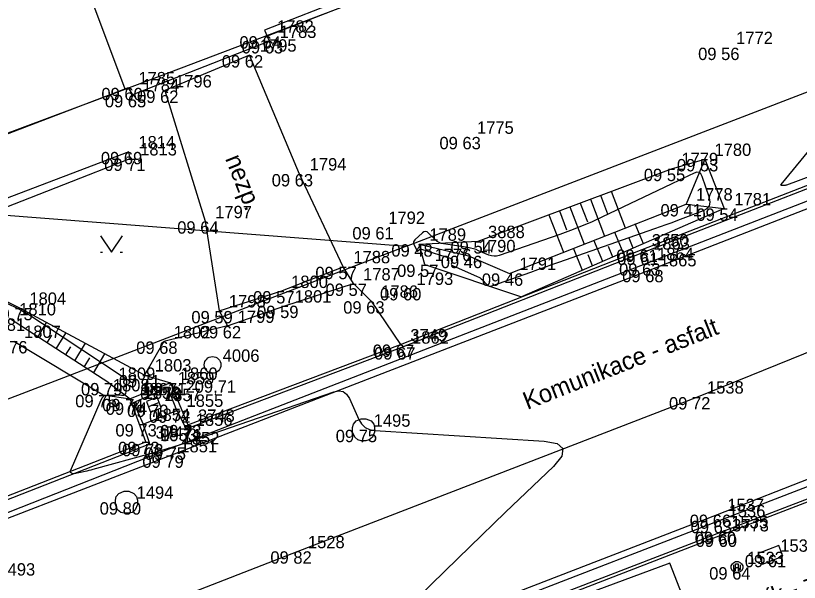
# Model space of a CAD drawing. Extents: x -703403 to -701924, y -1022520 to -1021856.
# Drawn here: x -702994.62 to -702976.87, y -1022001.97 to -1021989.15 of the extents above; entities that cross this region are included whole.
import ezdxf

# ---------------------------------------------------------------- set-up
doc = ezdxf.new("R2010")
doc.units = 0
for name, color, linetype in [('Ex_Minor Contours', 7, 'Continuous'), ('Z_bodove_pole', 7, 'Continuous'), ('Z_bodove_pole_cisla', 7, 'Continuous'), ('Z_bodove_pole_vysky', 7, 'Continuous'), ('Z_body', 7, 'Continuous'), ('Z_body_cisla', 7, 'Continuous'), ('Z_body_vysky_redukovane', 7, 'Continuous'), ('Z_budova', 7, 'Continuous'), ('Z_hrany_paty', 7, 'Continuous'), ('Z_katastr_hranice', 7, 'Continuous'), ('Z_katastr_vnitrni_kresba', 7, 'Continuous'), ('Z_komunikace', 7, 'Continuous'), ('Z_komunikace_osa', 7, 'Continuous'), ('Z_obruba', 7, 'Continuous'), ('Z_pilire', 7, 'Continuous'), ('Z_ploty', 7, 'Continuous'), ('Z_popisy', 7, 'Continuous'), ('Z_rozhranni', 7, 'Continuous'), ('Z_site_kanalizace_znaky', 7, 'Continuous'), ('Z_sloupy', 7, 'Continuous'), ('Z_technicke_srafy', 7, 'Continuous'), ('Z_vstupy', 7, 'Continuous'), ('Z_zlabek', 7, 'Continuous'), ('Z_znaky_kultur', 7, 'Continuous')]:
    doc.layers.add(name, color=color, linetype=linetype)

# ---------------------------------------------------------------- blocks, each defined once
blk = doc.blocks.new('POINT_DISPLAY')
blk.add_line((0, 0), (0, 0))
blk = doc.blocks.new('Z666')
for p, q in [((-0.25, 0.13), (-0.25, -0.13)), ((0.25, 0.13), (-0.25, 0.13)), ((0.25, -0.13), (0.25, 0.13)), ((-0.25, -0.13), (0.25, -0.13))]:
    blk.add_line(p, q)
blk = doc.blocks.new('Z620')
for p, q in [((-0.23, 0.13), (-0.17, 0.2)), ((-0.17, 0.2), (-0.05, 0.25)), ((-0.05, 0.25), (0.05, 0.25)), ((0.05, 0.25), (0.17, 0.2)), ((0.17, 0.2), (0.23, 0.13)), ((-0.25, 0.05), (-0.23, 0.13)), ((-0.25, -0.05), (-0.25, 0.05)), ((0.23, 0.13), (0.25, 0.05)), ((0.25, 0.05), (0.25, -0.05)), ((-0.2, -0.17), (-0.25, -0.05)), ((-0.13, -0.23), (-0.2, -0.17)), ((0.2, -0.17), (0.13, -0.23)), ((0.25, -0.05), (0.2, -0.17)), ((-0.05, -0.25), (-0.13, -0.23)), ((0.05, -0.25), (-0.05, -0.25)), ((0.13, -0.23), (0.05, -0.25))]:
    blk.add_line(p, q)
blk = doc.blocks.new('Z46260')
for p, q in [((0.13, 0.13), (-0.13, 0.13)), ((-0.13, 0.13), (-0.13, -0.13)), ((0.13, 0), (-0.13, 0)), ((0.13, -0.13), (0.13, 0.13)), ((-0.13, -0.13), (0.13, -0.13))]:
    blk.add_line(p, q)
blk = doc.blocks.new('Z601')
for p, q in [((-0.13, 0.03), (-0.1, 0.08)), ((-0.13, -0.03), (-0.13, 0.03)), ((-0.1, 0.08), (-0.08, 0.1)), ((-0.08, 0.1), (-0.03, 0.13)), ((-0.08, 0.05), (-0.08, -0.05)), ((-0.03, 0.13), (0.03, 0.13)), ((-0.03, -0.08), (-0.03, 0.08)), ((-0.03, 0.08), (0.03, 0.08)), ((0.03, 0.13), (0.08, 0.1)), ((0.03, 0.08), (0.03, -0.08)), ((0.08, 0.1), (0.1, 0.08)), ((0.08, -0.05), (0.08, 0.05)), ((0.1, 0.08), (0.13, 0.03)), ((0.13, 0.03), (0.13, -0.03)), ((-0.1, -0.08), (-0.13, -0.03)), ((-0.08, -0.1), (-0.1, -0.08)), ((-0.08, -0.05), (-0.03, -0.08)), ((-0.03, -0.13), (-0.08, -0.1)), ((0.03, -0.13), (-0.03, -0.13)), ((0.03, -0.08), (0.08, -0.05)), ((0.08, -0.1), (0.03, -0.13)), ((0.1, -0.08), (0.08, -0.1)), ((0.13, -0.03), (0.1, -0.08))]:
    blk.add_line(p, q)
blk = doc.blocks.new('Z314')
for p, q in [((-0.25, 0.17), (0, -0.2)), ((0, -0.2), (0.25, 0.17)), ((-0.25, -0.2), (-0.2, -0.2)), ((0.2, -0.2), (0.25, -0.2))]:
    blk.add_line(p, q)
blk = doc.blocks.new('Z101')
for radius in [0.188, 0.0025]:
    blk.add_circle((0, 0), radius)

msp = doc.modelspace()

# ---------------------------------------------------------------- linework, layer by layer
at = {"layer": 'Ex_Minor Contours'}
for points in [[(-702972.675, -1021991.314), (-702977.158, -1021992.979), (-702977.172, -1021992.984), (-702977.185, -1021992.987), (-702977.199, -1021992.988), (-702977.213, -1021992.988), (-702977.27, -1021992.987), (-702977.282, -1021992.985), (-702977.287, -1021992.98), (-702977.287, -1021992.973), (-702977.281, -1021992.964), (-702976.132, -1021991.569)], [(-702994.835, -1021995.642), (-702994.554, -1021995.785), (-702994.279, -1021995.941), (-702994.011, -1021996.11), (-702992.184, -1021997.318), (-702992.15, -1021997.347), (-702992.126, -1021997.381), (-702992.113, -1021997.42), (-702992.11, -1021997.465), (-702992.121, -1021997.654), (-702992.129, -1021997.695), (-702992.148, -1021997.724), (-702992.179, -1021997.74), (-702992.221, -1021997.745), (-702992.512, -1021997.735), (-702992.571, -1021997.74), (-702992.621, -1021997.761), (-702992.661, -1021997.797), (-702992.691, -1021997.848), (-702993.386, -1021999.459), (-702993.387, -1021999.463), (-702993.386, -1021999.466), (-702993.384, -1021999.474), (-702993.382, -1021999.477), (-702993.379, -1021999.479), (-702993.332, -1021999.506), (-702993.323, -1021999.509), (-702993.315, -1021999.512), (-702993.305, -1021999.512), (-702993.296, -1021999.511), (-702993.043, -1021999.456), (-702992.997, -1021999.446), (-702992.952, -1021999.435), (-702992.907, -1021999.423), (-702992.862, -1021999.411), (-702991.541, -1021999.049), (-702991.306, -1021998.983), (-702991.072, -1021998.912), (-702990.84, -1021998.839), (-702990.609, -1021998.761), (-702987.413, -1021997.658), (-702987.299, -1021997.635), (-702987.202, -1021997.653), (-702987.123, -1021997.711), (-702987.06, -1021997.81), (-702986.847, -1021998.283), (-702986.784, -1021998.388), (-702986.702, -1021998.465), (-702986.601, -1021998.514), (-702986.481, -1021998.536), (-702982.648, -1021998.78), (-702982.354, -1021998.833), (-702982.222, -1021998.945), (-702982.25, -1021999.117), (-702982.44, -1021999.347), (-702983.523, -1022000.387), (-702983.793, -1022000.647), (-702984.063, -1022000.908), (-702984.333, -1022001.169), (-702984.602, -1022001.43), (-702986.726, -1022003.497)]]:
    msp.add_lwpolyline(points, dxfattribs=at)
msp.add_lwpolyline([(-702983.924, -1021995.255), (-702983.896, -1021995.267), (-702983.865, -1021995.27), (-702983.833, -1021995.263), (-702982.948, -1021994.949), (-702982.789, -1021994.892), (-702982.63, -1021994.836), (-702982.471, -1021994.78), (-702982.312, -1021994.725), (-702980.144, -1021993.966), (-702980.012, -1021993.919), (-702979.881, -1021993.872), (-702979.749, -1021993.824), (-702979.619, -1021993.775), (-702979.04, -1021993.557), (-702978.955, -1021993.51), (-702978.904, -1021993.447), (-702978.887, -1021993.367), (-702978.905, -1021993.271), (-702979.069, -1021992.783), (-702979.097, -1021992.727), (-702979.136, -1021992.695), (-702979.186, -1021992.689), (-702979.247, -1021992.708), (-702979.51, -1021992.833), (-702979.576, -1021992.864), (-702979.642, -1021992.896), (-702979.708, -1021992.927), (-702979.774, -1021992.959), (-702981.325, -1021993.7), (-702981.563, -1021993.81), (-702981.804, -1021993.913), (-702982.049, -1021994.009), (-702982.295, -1021994.099), (-702983.665, -1021994.574), (-702983.725, -1021994.589), (-702983.784, -1021994.592), (-702983.843, -1021994.584), (-702983.901, -1021994.565), (-702984.134, -1021994.465), (-702984.192, -1021994.442), (-702984.252, -1021994.423), (-702984.313, -1021994.407), (-702984.375, -1021994.396), (-702984.928, -1021994.313), (-702984.979, -1021994.301), (-702985.026, -1021994.282), (-702985.069, -1021994.255), (-702985.109, -1021994.222), (-702985.265, -1021994.065), (-702985.3, -1021994.039), (-702985.335, -1021994.03), (-702985.371, -1021994.037), (-702985.407, -1021994.062), (-702985.578, -1021994.219), (-702985.596, -1021994.24), (-702985.606, -1021994.264), (-702985.607, -1021994.289), (-702985.599, -1021994.316), (-702985.536, -1021994.462), (-702985.531, -1021994.471), (-702985.524, -1021994.475), (-702985.517, -1021994.475), (-702985.508, -1021994.469), (-702985.47, -1021994.438), (-702985.46, -1021994.432), (-702985.45, -1021994.428), (-702985.439, -1021994.427), (-702985.428, -1021994.43), (-702984.754, -1021994.642), (-702984.74, -1021994.649), (-702984.731, -1021994.659), (-702984.728, -1021994.671), (-702984.73, -1021994.687), (-702984.75, -1021994.755), (-702984.752, -1021994.77), (-702984.749, -1021994.784), (-702984.741, -1021994.794), (-702984.727, -1021994.803), (-702984.162, -1021995.046), (-702984.13, -1021995.062), (-702984.1, -1021995.08), (-702984.072, -1021995.102), (-702984.047, -1021995.127), (-702983.949, -1021995.234)], close=True, dxfattribs=at)
at = {"layer": 'Z_budova'}
msp.add_line((-702992.07, -1021990.78), (-702997.53, -1021992.86), dxfattribs=at)
at = {"layer": 'Z_hrany_paty'}
for p, q in [((-702979.76, -1021992.61), (-702979.01, -1021992.39)), ((-702979.01, -1021992.39), (-702979.43, -1021993.41)), ((-702979.01, -1021992.39), (-702978.57, -1021993.51)), ((-702984.14, -1021994.25), (-702979.76, -1021992.61)), ((-702983.43, -1021994.98), (-702979.43, -1021993.41)), ((-702978.57, -1021993.51), (-702983.16, -1021995.51)), ((-702979.43, -1021993.41), (-702978.57, -1021993.51)), ((-702985.48, -1021994.32), (-702984.14, -1021994.25)), ((-702985.48, -1021994.32), (-702984.36, -1021994.58)), ((-702985.35, -1021994.78), (-702985.48, -1021994.32)), ((-702984.36, -1021994.58), (-702983.43, -1021994.98)), ((-702985.35, -1021994.78), (-702983.16, -1021995.51)), ((-702992.51, -1021997.46), (-702994.76, -1021996)), ((-702992.51, -1021997.46), (-702992.03, -1021997.82))]:
    msp.add_line(p, q, dxfattribs=at)
at = {"layer": 'Z_katastr_hranice'}
for p, q in [((-702985.77, -1021994.36), (-702958.49, -1021983.88)), ((-702992.14, -1021990.81), (-702986.88, -1021988.82)), ((-702997.54, -1021992.82), (-702992.14, -1021990.81)), ((-702998.95, -1021993.34), (-702985.77, -1021994.36)), ((-702985.77, -1021994.36), (-703007.65, -1022002.76)), ((-702979.8, -1022001.54), (-702991.54, -1022005.86)), ((-702978.94, -1022003.75), (-702979.8, -1022001.54))]:
    msp.add_line(p, q, dxfattribs=at)
at = {"layer": 'Z_katastr_vnitrni_kresba'}
msp.add_line((-702992.14, -1021990.81), (-703000.14, -1021969.33), dxfattribs=at)
at = {"layer": 'Z_komunikace'}
for p, q in [((-702980.25, -1021994.9), (-702966.7, -1021989.63)), ((-702991.12, -1021999.1), (-702980.25, -1021994.9)), ((-702978.72, -1022000.44), (-702970.7, -1021997.29)), ((-702998.41, -1022001.91), (-702991.12, -1021999.1)), ((-702987.66, -1022003.88), (-702978.72, -1022000.44))]:
    msp.add_line(p, q, dxfattribs=at)
at = {"layer": 'Z_komunikace_osa'}
for p, q in [((-702979.19, -1021997.78), (-702967.67, -1021993.13)), ((-702988.22, -1022001.27), (-702979.19, -1021997.78)), ((-702994.51, -1022003.7), (-702988.22, -1022001.27))]:
    msp.add_line(p, q, dxfattribs=at)
at = {"layer": 'Z_obruba'}
for p, q in [((-702980.43, -1021994.44), (-702966.9, -1021989.18)), ((-702980.32, -1021994.75), (-702966.79, -1021989.5)), ((-702992.06, -1021992.23), (-702996.78, -1021994.02)), ((-702992.03, -1021992.38), (-702992.06, -1021992.23)), ((-702996.72, -1021994.22), (-702992.03, -1021992.38)), ((-702985.9, -1021996.59), (-702980.43, -1021994.44)), ((-702991.07, -1021998.92), (-702980.32, -1021994.75)), ((-702990.72, -1021998.41), (-702985.9, -1021996.59)), ((-702991.11, -1021997.46), (-702992.03, -1021997.82)), ((-702991.11, -1021997.46), (-702990.72, -1021998.41)), ((-702978.7, -1022000.58), (-702970.64, -1021997.47)), ((-702991.67, -1021998.79), (-702992.03, -1021997.82)), ((-702978.61, -1022000.89), (-702970.57, -1021997.79)), ((-702998.54, -1022001.48), (-702991.67, -1021998.79)), ((-702998.44, -1022001.82), (-702991.07, -1021998.92)), ((-702987.62, -1022004.02), (-702978.7, -1022000.58)), ((-702984.36, -1022003.11), (-702978.61, -1022000.89))]:
    msp.add_line(p, q, dxfattribs=at)
at = {"layer": 'Z_ploty'}
for p, q in [((-702986.83, -1021988.63), (-702988.98, -1021989.47)), ((-702986.78, -1021988.77), (-702988.92, -1021989.61)), ((-702988.98, -1021989.47), (-702988.92, -1021989.61))]:
    msp.add_line(p, q, dxfattribs=at)
at = {"layer": 'Z_rozhranni'}
for p, q in [((-702989.32, -1021990.04), (-702991.24, -1021990.84)), ((-702988.19, -1021992.73), (-702989.32, -1021990.04)), ((-702991.24, -1021990.84), (-702990.33, -1021993.8)), ((-702987.2, -1021994.83), (-702988.19, -1021992.73)), ((-702990.33, -1021993.8), (-702990.01, -1021995.83)), ((-702994.54, -1021995.76), (-702997.09, -1021994.51)), ((-702986.97, -1021995.21), (-702987.2, -1021994.83)), ((-702986.57, -1021995.61), (-702986.97, -1021995.21)), ((-702986.57, -1021995.61), (-702985.9, -1021996.59)), ((-702991.7, -1021997.28), (-702994.54, -1021995.76)), ((-702990.01, -1021995.83), (-702989.82, -1021996.17)), ((-702989.82, -1021996.17), (-702991.26, -1021996.52)), ((-702994.66, -1021996.51), (-702992.64, -1021997.73)), ((-702991.26, -1021996.52), (-702991.7, -1021997.28)), ((-702991.7, -1021997.28), (-702991.11, -1021997.46)), ((-702991.95, -1021997.9), (-702991.17, -1021997.56)), ((-702990.97, -1021998.08), (-702991.17, -1021997.56)), ((-702992.64, -1021997.73), (-702992.03, -1021997.82)), ((-702991.95, -1021997.9), (-702991.73, -1021998.39))]:
    msp.add_line(p, q, dxfattribs=at)
at = {"layer": 'Z_technicke_srafy'}
for p, q in [((-702981.37, -1021993.21), (-702981.21, -1021993.63)), ((-702981.13, -1021993.12), (-702980.81, -1021993.95)), ((-702981.83, -1021993.39), (-702981.67, -1021993.81)), ((-702981.6, -1021993.3), (-702981.28, -1021994.14)), ((-702982.3, -1021993.56), (-702982.14, -1021993.99)), ((-702982.07, -1021993.47), (-702981.74, -1021994.32)), ((-702982.54, -1021993.65), (-702982.21, -1021994.5)), ((-702980.4, -1021994.31), (-702980.59, -1021993.86)), ((-702980.86, -1021994.51), (-702981.05, -1021994.05)), ((-702981.32, -1021994.71), (-702981.52, -1021994.23)), ((-702980.63, -1021994.41), (-702980.72, -1021994.18)), ((-702981.78, -1021994.91), (-702981.98, -1021994.41)), ((-702981.09, -1021994.61), (-702981.19, -1021994.37)), ((-702981.55, -1021994.81), (-702981.65, -1021994.56)), ((-702994.12, -1021996.42), (-702993.92, -1021996.09)), ((-702993.91, -1021996.55), (-702993.8, -1021996.38)), ((-702993.7, -1021996.69), (-702993.48, -1021996.33)), ((-702993.28, -1021996.96), (-702993.04, -1021996.56)), ((-702993.49, -1021996.83), (-702993.37, -1021996.64)), ((-702993.07, -1021997.1), (-702992.94, -1021996.89)), ((-702992.86, -1021997.24), (-702992.6, -1021996.8))]:
    msp.add_line(p, q, dxfattribs=at)
at = {"layer": 'Z_vstupy'}
for p, q in [((-702988.87, -1021989.72), (-702988.92, -1021989.61)), ((-702988.87, -1021989.72), (-702991.97, -1021990.94)), ((-702992.07, -1021990.78), (-702991.97, -1021990.94))]:
    msp.add_line(p, q, dxfattribs=at)
at = {"layer": 'Z_zlabek'}
for p, q in [((-702980.41, -1021994.51), (-702966.87, -1021989.24)), ((-702985.87, -1021996.65), (-702980.41, -1021994.51)), ((-702988.61, -1021995.38), (-702987.2, -1021994.83)), ((-702988.52, -1021995.71), (-702986.97, -1021995.21)), ((-702990.01, -1021995.83), (-702988.61, -1021995.38)), ((-702989.82, -1021996.17), (-702988.52, -1021995.71)), ((-702990.76, -1021998.5), (-702985.87, -1021996.65)), ((-702978.63, -1022000.83), (-702970.56, -1021997.71)), ((-702991.73, -1021998.39), (-702990.97, -1021998.08)), ((-702990.97, -1021998.08), (-702990.76, -1021998.5)), ((-702991.58, -1021998.84), (-702991.73, -1021998.39)), ((-702998.52, -1022001.54), (-702991.58, -1021998.84)), ((-702984.39, -1022003.04), (-702978.63, -1022000.83))]:
    msp.add_line(p, q, dxfattribs=at)

# ---------------------------------------------------------------- block references
at = {"layer": 'Z_bodove_pole'}
msp.add_blockref('Z101', (-702990.16, -1021997.05), dxfattribs=at)
at = {"layer": 'Z_body'}
for p in [(-702988.92, -1021989.61), (-702988.87, -1021989.72), (-702978.53, -1021989.87), (-702989.32, -1021990.04), (-702992.07, -1021990.78), (-702991.24, -1021990.84), (-702991.97, -1021990.94), (-702984.39, -1021991.89), (-702992.06, -1021992.23), (-702992.03, -1021992.38), (-702979.01, -1021992.39), (-702979.76, -1021992.61), (-702988.19, -1021992.73), (-702979.43, -1021993.41), (-702978.57, -1021993.51), (-702990.33, -1021993.8), (-702986.41, -1021993.93), (-702984.14, -1021994.25), (-702985.48, -1021994.32), (-702980.43, -1021994.44), (-702984.36, -1021994.58), (-702980.41, -1021994.51), (-702985.35, -1021994.78), (-702980.32, -1021994.75), (-702987.2, -1021994.83), (-702983.43, -1021994.98), (-702980.25, -1021994.9), (-702986.97, -1021995.21), (-702985.76, -1021995.31), (-702988.61, -1021995.38), (-702986.57, -1021995.61), (-702994.54, -1021995.76), (-702990.01, -1021995.83), (-702988.52, -1021995.71), (-702989.82, -1021996.17), (-702991.26, -1021996.52), (-702985.9, -1021996.59), (-702985.87, -1021996.65), (-702990.16, -1021997.05), (-702991.7, -1021997.28), (-702992.51, -1021997.46), (-702991.11, -1021997.46), (-702991.17, -1021997.56), (-702992.64, -1021997.73), (-702992.03, -1021997.82), (-702979.19, -1021997.78), (-702991.95, -1021997.9), (-702991.49, -1021997.95), (-702990.97, -1021998.08), (-702991.73, -1021998.39), (-702990.76, -1021998.5), (-702990.72, -1021998.41), (-702986.74, -1021998.52), (-702991.67, -1021998.79), (-702991.58, -1021998.84), (-702991.07, -1021998.92), (-702991.12, -1021999.1), (-702992.11, -1022000.16), (-702978.72, -1022000.44), (-702978.7, -1022000.58), (-702978.63, -1022000.83), (-702978.61, -1022000.89), (-702988.22, -1022001.27), (-702977.52, -1022001.35), (-702978.28, -1022001.63)]:
    msp.add_blockref('POINT_DISPLAY', p, dxfattribs=at)
at = {"layer": 'Z_pilire', "rotation": 21.6}
msp.add_blockref('Z666', (-702977.52, -1022001.35), dxfattribs=at)
at = {"layer": 'Z_site_kanalizace_znaky', "rotation": 21.6}
msp.add_blockref('Z46260', (-702991.49, -1021997.95), dxfattribs=at)
at = {"layer": 'Z_site_kanalizace_znaky'}
for p in [(-702986.74, -1021998.52), (-702992.11, -1022000.16)]:
    msp.add_blockref('Z620', p, dxfattribs=at)
at = {"layer": 'Z_sloupy'}
msp.add_blockref('Z601', (-702978.28, -1022001.63), dxfattribs=at)
at = {"layer": 'Z_znaky_kultur'}
msp.add_blockref('Z314', (-702992.45, -1021994.3), dxfattribs=at)

# ---------------------------------------------------------------- texts
at = {"layer": 'Z_bodove_pole_cisla'}
msp.add_text('4006', height=0.28, dxfattribs=at).set_placement((-702989.93, -1021996.98))
at = {"layer": 'Z_bodove_pole_vysky'}
msp.add_text('209,71', height=0.28, dxfattribs=at).set_placement((-702990.773, -1021997.68))
at = {"layer": 'Z_body_cisla'}
for s, p in [('1782', (-702988.7, -1021989.53)), ('1783', (-702988.64, -1021989.65)), ('1772', (-702978.3, -1021989.79)), ('1795', (-702989.09, -1021989.96)), ('1785', (-702991.84, -1021990.7)), ('1796', (-702991.01, -1021990.77)), ('1784', (-702991.75, -1021990.86)), ('1775', (-702984.17, -1021991.82)), ('1814', (-702991.84, -1021992.15)), ('1813', (-702991.8, -1021992.31)), ('1780', (-702978.79, -1021992.32)), ('1779', (-702979.54, -1021992.53)), ('1794', (-702987.96, -1021992.65)), ('1778', (-702979.21, -1021993.33)), ('1781', (-702978.34, -1021993.44)), ('1797', (-702990.1, -1021993.73)), ('1792', (-702986.18, -1021993.86)), ('3888', (-702983.92, -1021994.18)), ('1789', (-702985.25, -1021994.24)), ('3750', (-702980.21, -1021994.37)), ('1790', (-702984.13, -1021994.5)), ('1863', (-702980.18, -1021994.44)), ('1776', (-702985.13, -1021994.7)), ('1864', (-702980.09, -1021994.68)), ('1788', (-702986.97, -1021994.75)), ('1791', (-702983.21, -1021994.9)), ('1865', (-702980.03, -1021994.82)), ('1787', (-702986.75, -1021995.14)), ('1793', (-702985.54, -1021995.24)), ('1800', (-702988.38, -1021995.31)), ('1786', (-702986.34, -1021995.53)), ('1804', (-702994.31, -1021995.69)), ('1798', (-702989.79, -1021995.75)), ('1801', (-702988.3, -1021995.64)), ('1810', (-702994.54, -1021995.93)), ('1799', (-702989.59, -1021996.1)), ('1807', (-702994.43, -1021996.44)), ('1802', (-702991.04, -1021996.45)), ('3749', (-702985.68, -1021996.52)), ('1862', (-702985.64, -1021996.57)), ('1803', (-702991.47, -1021997.2)), ('1809', (-702992.29, -1021997.39)), ('1860', (-702990.88, -1021997.39)), ('1859', (-702990.95, -1021997.49)), ('1808', (-702992.42, -1021997.65)), ('1861', (-702991.8, -1021997.74)), ('1538', (-702978.96, -1021997.7)), ('1858', (-702991.72, -1021997.82)), ('1857', (-702991.26, -1021997.87)), ('1855', (-702990.75, -1021998)), ('1854', (-702991.5, -1021998.32)), ('1856', (-702990.54, -1021998.43)), ('3748', (-702990.49, -1021998.34)), ('1495', (-702986.51, -1021998.45)), ('3747', (-702991.45, -1021998.72)), ('1853', (-702991.35, -1021998.77)), ('1852', (-702990.84, -1021998.85)), ('1851', (-702990.89, -1021999.03)), ('1494', (-702991.88, -1022000.08)), ('1537', (-702978.5, -1022000.36)), ('1536', (-702978.47, -1022000.5)), ('1535', (-702978.41, -1022000.75)), ('3773', (-702978.39, -1022000.82)), ('1528', (-702988, -1022001.2)), ('1534', (-702977.3, -1022001.28)), ('1533', (-702978.05, -1022001.56)), ('1493', (-702995.01, -1022001.82))]:
    msp.add_text(s, height=0.28, dxfattribs=at).set_placement(p)
at = {"layer": 'Z_body_vysky_redukovane'}
for s, p in [('09 64', (-702989.55, -1021989.89)), ('09 63', (-702989.5, -1021990)), ('09 56', (-702979.16, -1021990.15)), ('09 62', (-702989.95, -1021990.32)), ('09 60', (-702992.677, -1021991.06)), ('09 62', (-702991.87, -1021991.12)), ('09 65', (-702992.6, -1021991.22)), ('09 63', (-702985.02, -1021992.17)), ('09 69', (-702992.69, -1021992.51)), ('09 71', (-702992.613, -1021992.66)), ('09 53', (-702979.64, -1021992.67)), ('09 55', (-702980.39, -1021992.89)), ('09 63', (-702988.82, -1021993.01)), ('09 41', (-702980.013, -1021993.69)), ('09 54', (-702979.2, -1021993.79)), ('09 64', (-702990.96, -1021994.08)), ('09 61', (-702986.993, -1021994.21)), ('09 54', (-702984.77, -1021994.53)), ('09 48', (-702986.11, -1021994.6)), ('09 61', (-702981.013, -1021994.72)), ('09 46', (-702984.99, -1021994.86)), ('09 61', (-702980.993, -1021994.79)), ('09 57', (-702985.98, -1021995.06)), ('09 63', (-702980.95, -1021995.03)), ('09 57', (-702987.83, -1021995.11)), ('09 46', (-702984.06, -1021995.26)), ('09 68', (-702980.88, -1021995.18)), ('09 57', (-702987.6, -1021995.49)), ('09 60', (-702986.367, -1021995.59)), ('09 57', (-702989.24, -1021995.66)), ('09 63', (-702987.2, -1021995.89)), ('09 75', (-702995.17, -1021996.04)), ('09 59', (-702990.64, -1021996.11)), ('09 59', (-702989.15, -1021995.99)), ('09 81', (-702995.343, -1021996.28)), ('09 62', (-702990.45, -1021996.45)), ('09 76', (-702995.29, -1021996.79)), ('09 68', (-702991.89, -1021996.8)), ('09 67', (-702986.53, -1021996.87)), ('09 67', (-702986.5, -1021996.93)), ('09 71', (-702992.283, -1021997.56)), ('09 79', (-702993.14, -1021997.74)), ('09 71', (-702991.693, -1021997.74)), ('09 73', (-702991.8, -1021997.84)), ('09 75', (-702993.27, -1021998.01)), ('09 74', (-702992.66, -1021998.1)), ('09 72', (-702979.82, -1021998.06)), ('09 74', (-702992.58, -1021998.18)), ('09 70', (-702992.097, -1021998.23)), ('09 72', (-702991.6, -1021998.36)), ('09 73', (-702992.36, -1021998.67)), ('09 73', (-702991.35, -1021998.69)), ('09 71', (-702991.343, -1021998.78)), ('09 75', (-702987.37, -1021998.8)), ('09 73', (-702992.3, -1021999.07)), ('09 73', (-702992.21, -1021999.12)), ('09 75', (-702991.7, -1021999.2)), ('09 79', (-702991.75, -1021999.38)), ('09 80', (-702992.717, -1022000.44)), ('09 66', (-702979.35, -1022000.72)), ('09 63', (-702979.33, -1022000.86)), ('09 60', (-702979.237, -1022001.11)), ('09 60', (-702979.217, -1022001.17)), ('09 82', (-702988.85, -1022001.55)), ('09 61', (-702978.103, -1022001.63)), ('09 64', (-702978.91, -1022001.91))]:
    msp.add_text(s, height=0.28, dxfattribs=at).set_placement(p)
at = {"layer": 'Z_popisy'}
for s, rotation, p in [('nezp.', 291.6, (-702989.88, -1021992.38)), ('Komunikace - asfalt', 21.6, (-702983.03, -1021998.07)), ('Chodník - zámk. dlažba', 19.8, (-702979.03, -1022003.06))]:
    msp.add_text(s, height=0.4, rotation=rotation, dxfattribs=at).set_placement(p)

doc.saveas('drawing.dxf')
